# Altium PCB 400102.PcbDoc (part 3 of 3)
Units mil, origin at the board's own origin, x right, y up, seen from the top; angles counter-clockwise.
Board outline 3703.69 x 2381.89 mil, 2 copper layers (Top Layer, Bottom Layer), stack 61.8 mil thick; 220 components, 149 nets, 880 pads, 750 vias.
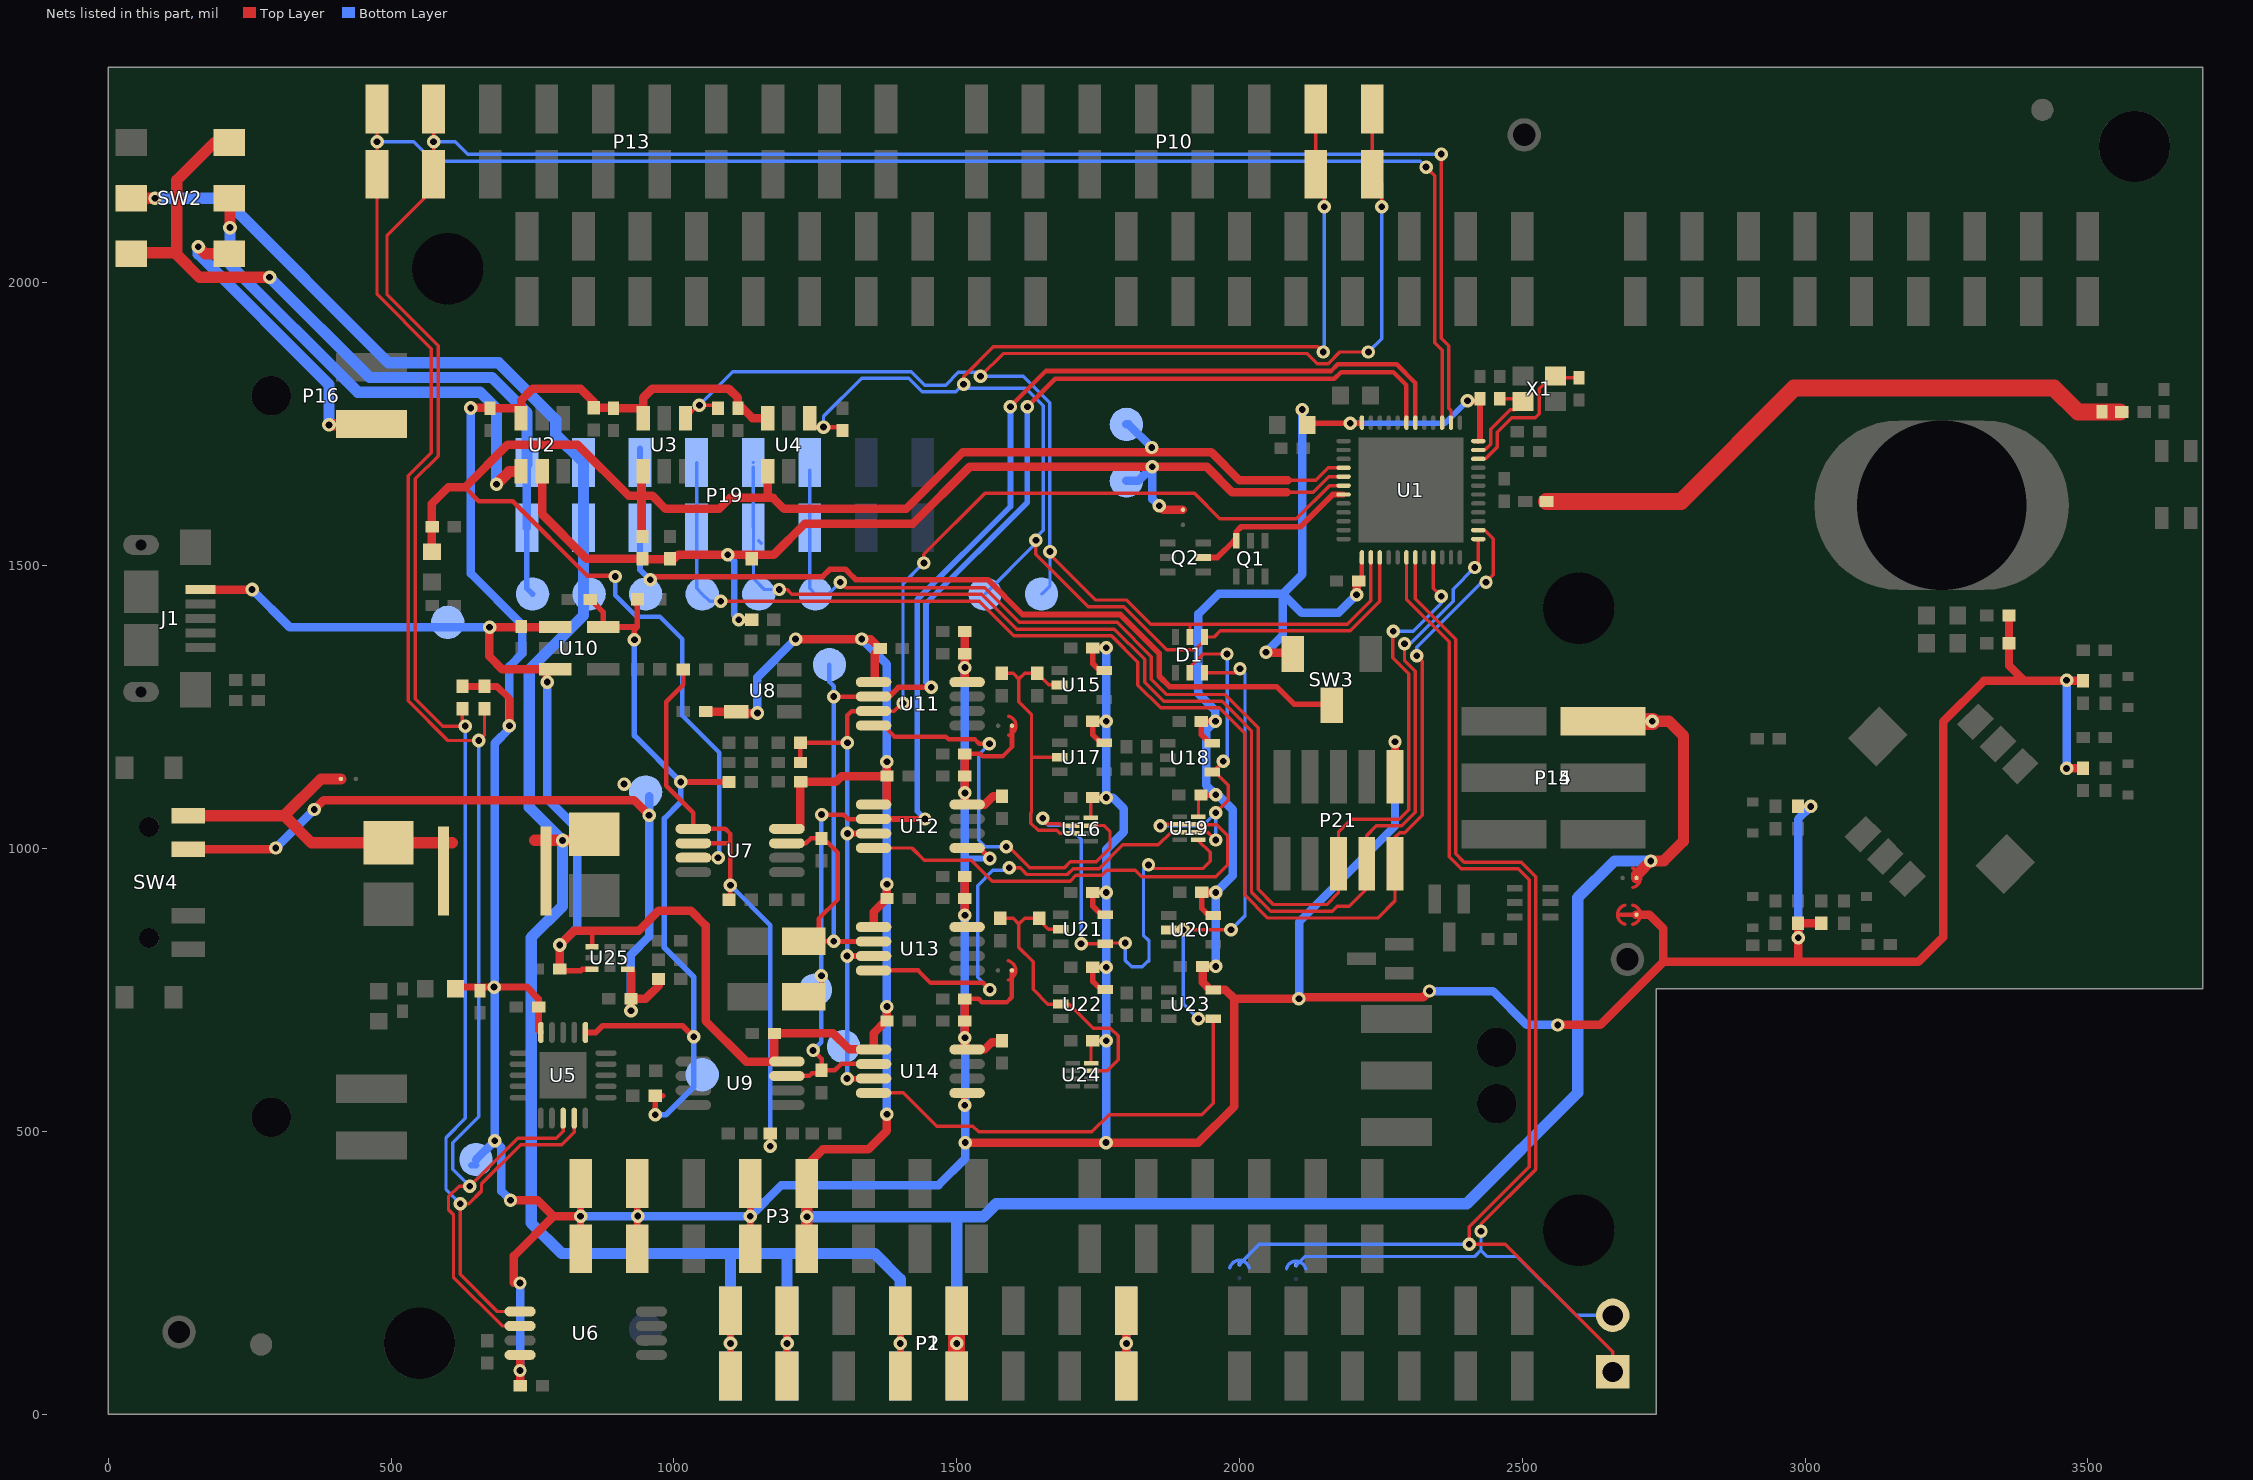
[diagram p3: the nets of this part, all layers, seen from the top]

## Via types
v1: diameter 24, hole 12, Top Layer to Bottom Layer, tented both sides, 666 vias
v2: diameter 23.62, hole 11.81, Top Layer to Bottom Layer, tented both sides, 68 vias
v3: diameter 25.98, hole 12.99, Top Layer to Bottom Layer, tented both sides, 16 vias

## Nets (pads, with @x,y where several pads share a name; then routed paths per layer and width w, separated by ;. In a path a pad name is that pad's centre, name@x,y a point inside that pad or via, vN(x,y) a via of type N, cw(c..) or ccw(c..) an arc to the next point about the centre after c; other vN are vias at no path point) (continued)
P0.05: Q1.6 Q2.2 U1.7 | length 303.6
  Top Layer w10: Q2.2@1936,1514.59 1960.59,1514.59 1989.99,1543.99 Q1.6@1994,1543.99 1994,1560 2003,1569 2108,1569 2164.98,1625.98 U1.7@2184.06,1625.98
RF: C14.2 L1.2 R7.1 | length 1114.4
  Top Layer w30: L1.2@2542.85,1613.86 2780.7,1613.86 2980.82,1813.98 3440.48,1813.98 3482.5,1771.95 R7.1@3556.93,1771.95
SCL: P13.10 R9.1 U1.39 U5.3 U6.6 | length 5047.8
  Top Layer w6: P13.10@475,2307.52 v1(475,2249.84) P13.10@475,2192.17 475,1980 571,1884 571,1700 530,1659 530,1261.16 600.16,1191 v1(655,1191) 665,1201 R9.1@665,1247.32 ; U6.6@727.86,155.8 696.2,155.8 610.09,241.91 610.09,352.91 601.28,361.72 601.28,384.28 620,403 v2(639,403) 724,488 792,488 804,500 U5.3@804,523.21 ; v1(2330,2205) 2345,2190 2345,1894.67 2358.27,1881.4 U1.39@2358.27,1752.95
  Bottom Layer w6: v1(475,2249.84) 540.16,2249.84 575,2215 2320,2215 v1(2330,2205) ; v2(639,403) 608.91,433.09 608.91,479.91 655,526 v1(655,1191)
SDA: P13.9 R8.1 U1.38 U5.4 U6.5 | length 4958.2
  Top Layer w6: P13.9@575,2307.52 v1(575,2249.84) P13.9@575,2192.17 575,2166.84 492.69,2084.53 492.69,1979.31 583,1889 583,1694 542.85,1653.85 542.85,1265.15 591.49,1216.51 v1(631,1216.51) 626,1221.51 R8.1@626,1247.32 ; U6.5@727.86,181.39 687.45,181.39 622,246.84 v2(622,372) 637.3,372 659.72,394.42 659.72,406.88 728.93,476.09 801.78,476.09 823.69,498 U5.4@823.69,523.21 ; v1(2356.91,2227.97) 2356.91,1902.19 2370.17,1888.92 2370.17,1778.41 2374.02,1774.56 U1.38@2374.02,1752.95
  Bottom Layer w6: v1(575,2249.84) 613.28,2249.84 635.16,2227.97 v1(2356.91,2227.97) ; v2(622,372) 597,397 597,489 631,523 v1(631,1216.51)
SE_OUT: C26.2 R24.2 TP12.1 U1.6 U11.3 U12.3 U13.3 U14.3 | length 2115.3
  Top Layer w6: U11.3@1352.98,1243.08 1389.08,1243.08 1403,1257 v2(1405,1257) ; v2(1442,1505) 1442,1520 1550,1628 1920.44,1628 1965.34,1583.09 2100.55,1583.09 2159.19,1641.73 U1.6@2184.06,1641.73
  Top Layer w8: C26.2@1223.69,1152.3 R24.2@1223.69,1186.89 1306.64,1186.89 v1(1306.8,1187.05) 1306.8,1235.52 1314.36,1243.08 U11.3@1352.98,1243.08
  Top Layer w10: v1(1306.23,593.12) 1352.62,593.12 U14.3@1352.98,593.48 ; v1(1306.23,810.01) U13.3@1352.98,810.01 ; v1(1306.8,1026.55) U12.3@1352.98,1026.55
  Bottom Layer w6: v2(1405,1257) 1405,1468 v2(1442,1505)
  Bottom Layer w8: v1(1306.23,593.12) v1(1306.23,810.01) 1306.8,810.58 v1(1306.8,1026.55) v1(1306.8,1187.05)
STAGE1_OUT: R39.2 R41.2 U15.2 U16.3 U17.2 | length 512.7
  Top Layer w6: R39.2@1579.77,1309.8 1600,1309.8 1610,1299.8 ; 1633.55,1161.41 U17.2@1682,1161.41 ; U15.2@1681.78,1289.41 1662.79,1289.41 R41.2@1642.41,1309.79 1620,1309.8 1610,1299.8 ; U16.3@1704.66,1026.87 1689,1026.87 1682.36,1026.87 1680.48,1028.74 1677.07,1032.15 1643.93,1032.15 1631.09,1044.99 1631.09,1062.31 1632.14,1063.35 1632.14,1237.49 1610,1259.63 1610,1299.8
STAGE2_OUT: R43.2 R45.2 U21.2 U22.2 U24.7 | length 529.3
  Top Layer w6: R43.2@1579.77,876.53 1600,876.53 1610,866.53 ; U21.2@1684.18,857.29 1662.21,857.29 1642.97,876.53 1620,876.53 1610,866.53 ; U24.7@1737.49,606.89 1765.89,606.89 1785.34,626.34 1785.34,668.66 1771.47,682.53 1741.47,682.53 1699.1,724.9 U22.2@1683.75,724.9 1661,724.9 1635,750.9 1635,800 1610,825 1610,866.53
STAGE2_OUT_INV: U16.2 U19.5 U21.4 | length 820.2
  Top Layer w6: v1@1654,1049.65 1659.59,1044.06 1682,1044.06 1685.41,1040.65 U16.2@1704.66,1040.65 ; v1(1720,831.7) U21.4@1762.92,831.7 1764.23,833 v2(1798,833) ; v2(1839,971) 1845.37,964.63 1934.82,964.63 1948,977.81 1948,993.26 1927.43,1013.83 U19.5@1927.43,1015.16
  Bottom Layer w6: v1@1654,1049.65 1663,1040.65 1696.05,1040.65 1720,1016.7 v1(1720,831.7) ; v2(1798,833) 1798,802 1809.33,790.67 1827.75,790.67 1838.08,801 1840,801 1840,837.13 1830.19,846.95 1830.19,962.19 v2(1839,971)
  other v1: 1652,1053.65
STG1_OFF_SHDN: U12.4 U19.7 | length 783.3
  Top Layer w6: U12.4@1352.98,1000.96 1420.91,1000.96 1442.86,979.01 1525.8,979.01 1562.62,942.19 1700.44,942.19 1710.82,952.57 1756.66,952.57 1765.67,961.58 1816,961.58 1827.3,950.28 1958.28,950.28 1978.72,970.72 1978.72,1023.58 1960.01,1042.28 1927.87,1042.28 U19.7@1927.43,1042.72
STG1_ON_SHDN: U11.4 U16.7 | length 731
  Top Layer w6: v1(1587.44,1003.23) 1591.79,1003.23 1629.02,966 1690.58,966 1700.96,976.38 1746.8,976.38 1770.95,1000.53 1770.95,1030.33 1760.63,1040.65 U16.7@1737.34,1040.65
  Top Layer w8: U11.4@1352.98,1217.49 1370.51,1217.49 1390,1198 1480.89,1198 1486,1192.89 1532.22,1192.89 1539.99,1185.12 v1(1557.77,1185.12)
  Bottom Layer w6: v1(1557.77,1185.12) 1538.66,1166.01 1538.66,1014.68 1550.11,1003.23 v1(1587.44,1003.23)
STG2_ON_SHDN: U13.4 U19.3 | length 819.3
  Top Layer w6: v2(1593,966) 1612.18,966 1624.09,954.09 1695.51,954.09 1705.89,964.48 1751.73,964.48 1793.63,1006.37 1856.65,1006.37 1879.21,1028.94 U19.3@1894.76,1028.94
  Top Layer w8: U13.4@1352.98,784.42 1431.65,784.42 1453.72,762.35 1547.07,762.35 v1(1558.77,750.66)
  Bottom Layer w6: v1(1558.77,750.66) 1537,772.43 1537,934.42 1564,961.42 1588.42,961.42 v2(1593,966)
SW1_ON/OFF: D1.2 P10.1 R5.2 TP3.1 U1.14 U3.4 | length 3005.8
  Top Layer w6: U3.4@1020.4,1761.22 1043.18,1784 v1(1045,1784) 1072.66,1784 R5.2@1078,1778.66 ; v1(1542,1835) 1582.28,1875.28 2119.72,1875.28 2137.72,1857.28 2156.58,1857.28 2177.3,1878 v2(2228,1878) ; v1(1665,1525) 1665,1519.38 1744.85,1439.53 1799.97,1439.53 1842.82,1396.69 1912,1396.69 ; D1.2@1912.41,1374 1912.41,1396.28 1912,1396.69 ; U1.14@2232.28,1514.76 2232.28,1438.12 2190.85,1396.69 1912,1396.69 ; P10.1@2235,2307.52 P10.1@2235,2192.17 2251.41,2175.75 v1(2251.41,2135)
  Bottom Layer w6: v1(1045,1784) 1104.19,1843.19 1419.97,1843.19 1443.67,1819.49 1480.49,1819.49 1502.91,1841.91 1536.52,1841.91 v1@1543.43,1835 ; v1(1542,1835) v1@1543.43,1835 ; TP3.1@1650,1450 1665,1465 v1(1665,1525) 1664.57,1525.43 1664.57,1788.09 1617.65,1835 v1@1543.43,1835 ; v2(2228,1878) 2251.41,1901.41 v1(2251.41,2135)
SW1_ON/OFF_AUTO: D1.5 U18.4 U19.2 U19.6 | length 628
  Top Layer w6: v1(1860,1040) 1862.72,1042.72 U19.2@1894.76,1042.72 ; D1.5@1912.41,1311.01 1912.41,1320.41 1936,1344 v2(1978,1344) ; U19.6@1927.43,1028.94 1944.06,1028.94 v2(1958,1015) ; v2(1958,1063) 1980,1085 1980,1112 1957.03,1134.97 U18.4@1952.15,1134.97 v1(1971.34,1154.16)
  Bottom Layer w6: v1(1860,1040) 1935,1040 v2(1958,1063) v2(1958,1015) ; v1(1971.34,1154.16) 1978.29,1161.11 1978.29,1343.71 v2(1978,1344)
SW2_ON/OFF: D1.1 P10.2 R6.1 TP4.1 U1.15 U4.4 | length 2837.3
  Top Layer w6: v1(1512.09,1821) 1512.09,1834.65 1564.62,1887.19 2138.81,1887.19 v2(2148,1878) ; v1(1640,1545) 1640,1520.44 1732.81,1427.62 1795.04,1427.62 1871.35,1351.31 1922,1351.31 1938,1367.31 D1.1@1938,1374 1955,1374 1965.78,1384.78 2195.78,1384.78 2248.03,1437.03 U1.15@2248.03,1514.76 ; P10.2@2135,2307.52 P10.2@2135,2192.17 2150,2177.16 v1(2150,2135)
  Top Layer w8: U4.4@1240.4,1761.22 1243,1758.62 1243,1747.86 1245.6,1745.26 v1(1264.42,1745.26) 1292.03,1745.26 R6.1@1298,1739.29
  Bottom Layer w6: v1(1264.42,1745.26) 1264.42,1764 1331.7,1831.28 1415.04,1831.28 1438.74,1807.58 1498.67,1807.58 v1(1512.09,1821) ; v1@1517.99,1814.09 1621.72,1814.09 1652.66,1783.15 1652.66,1562.5 1640,1549.84 v1(1640,1545) 1640,1540 TP4.1@1550,1450 ; v2(2148,1878) 2150,1880 v1(2150,2135)
SW2_ON/OFF_AUTO: D1.6 U14.4 U20.2 U23.4 | length 1645.4
  Top Layer w6: U14.4@1352.98,567.89 1405.68,567.89 1464.66,508.91 1528.6,508.91 1538.6,498.91 1738.91,498.91 1769.41,529.41 1932.92,529.41 1953.36,549.85 U23.4@1953.36,698.95 v1(1927.43,698.95) ; U20.2@1874.62,856.27 v1(1900.57,856.27) v1(1985,856.27) ; D1.6@1938,1311.01 1994.01,1311.01 v2(2001,1318)
  Bottom Layer w6: v1(1900.57,856.27) 1900.57,725.81 v1(1927.43,698.95) ; v1(1985,856.27) 2009.74,881.02 2009.74,1309.26 v2(2001,1318)
SWDCLK: P19.5 P21.4 TP7.1 U1.25 | length 2486.7
  Top Layer w6: v2(1186,1458) 1200,1458 1208.5,1449.5 1544.34,1449.5 1605.93,1387.91 1778.59,1387.91 1832.19,1334.31 1832.19,1294.03 1865.7,1260.51 1969.32,1260.51 1997.42,1232.42 2021.19,1208.65 2021.19,923.1 2055.24,889.05 2164,889.05 2172.95,898 2194,898 2225,929 P21.4@2225,973.23 2225,1023 2242.09,1040.09 2287.31,1040.09 2311,1063.78 2311,1313.87 2291.72,1333.15 v2(2291.72,1362) ; v2(2416,1497) 2422.24,1503.24 U1.25@2422.24,1547.24
  Bottom Layer w6: P19.5@1140,1673.98 P19.5@1140,1567.32 1140.75,1566.57 1140.75,1477.25 1160,1458 v2(1186,1458) ; P19.5@1150,1543.98 P19.5@1154.1,1539.88 ; v2(2291.72,1362) 2302.3,1362 2377.72,1437.42 2377.72,1458.72 v2(2416,1497)
SWDIO: P19.4 P21.2 TP6.1 U1.26 | length 2665.7
  Top Layer w6: v2(1083,1437) 1540,1437 1601,1376 1773.66,1376 1820.28,1329.38 1820.28,1289.1 1860.77,1248.61 1964.39,1248.61 2009.28,1203.72 2009.28,918.17 2050.36,877.09 2244.56,877.09 2275,907.53 P21.2@2275,973.23 2275,1020 2283.19,1028.19 2292.24,1028.19 2322.91,1058.85 2322.91,1331.53 v1(2313.43,1341) ; U1.26@2422.24,1562.99 2433.65,1562.99 2449,1547.64 2449,1484 v2(2436,1471)
  Bottom Layer w6: P19.4@1040,1682.68 P19.4@1040,1567.32 1040,1460 TP6.1@1050,1450 1063,1437 v2(1083,1437) ; v1(2313.43,1341) 2313.43,1356.3 2428.13,1471 v2(2436,1471)
SWO: P19.6 P21.6 TP8.1 U1.21 | length 2360.1
  Top Layer w6: v2(1294,1471) 1303.6,1461.4 1549.27,1461.4 1610.86,1399.81 1783.52,1399.81 1844.09,1339.24 1844.09,1298.96 1870.64,1272.42 1974.26,1272.42 2033.09,1213.58 2033.09,928.03 2060.17,900.96 2153.96,900.96 2175,922 P21.6@2175,973.23 2175,1029 2198,1052 2282.38,1052 2299.09,1068.72 2299.09,1308.94 2271,1337.03 2271,1383 v2(2272,1384) ; U1.21@2342.52,1514.76 2342.52,1460.48 v2(2357,1446)
  Bottom Layer w6: P19.6@1240,1668.98 P19.6@1240,1567.32 1240,1460 TP8.1@1250,1450 1273,1450 v2(1294,1471) ; v2(2272,1384) 2307.46,1384 2357,1433.54 v2(2357,1446)
SYNC1: P7.1 SB3.1 U1.18 | length 2196.2
  Top Layer w6: U1.18@2295.28,1514.76 2295.28,1440.72 2370.72,1365.28 2370.72,985.45 2392.07,964.09 2493.07,964.09 2512.09,945.07 2512.09,437.39 2406,331.3 v2(2406,300) 2470,300 2660,110 P7.1@2660,74.68
  Bottom Layer w6: SB3.1@2000,265 2035,300 v2(2406,300)
SYNC2: P7.2 SB4.1 U1.19 | length 2031.1
  Top Layer w6: U1.19@2311.02,1514.76 2311.02,1441.81 2382.62,1370.21 2382.62,990.38 2397,976 2498,976 2524,950 2524,432.46 2427,335.46 v2(2427,323)
  Bottom Layer w6: SB4.1@2100,263.36 2115.17,278.54 2415.54,278.54 2427,290 ; v2(2427,323) 2427,290 ; P7.2@2660,174.68 2595.32,174.68 2491.46,278.54 2438.46,278.54 2427,290
V5V: C23.2 C24.2 C28.2 C30.2 C32.1 C36.1 C41.1 C45.1 C59.1 J1.1 P1.5 P2.5 P3.5 P14.2 P15.2 SB8.1 TP16.1 U7.8 U8.5 U9.8 U10.1 U10.3 U11.1 U12.1 U13.1 U14.1 U25.1 U25.3 | length 7396.5
  Top Layer w8: U25.1@855.13,826.2 855.13,854.87
  Top Layer w10: C59.1@798.13,786.83 801.35,783.61 834.9,783.61 838.12,786.83 U25.3@855.13,786.83
  Top Layer w15: J1.1@163,1458 v1(254,1458) ; v1(776,1294.26) 775,1295.26 775,1316.96 696.2,1316.96 673.59,1339.57 673.59,1390.94 v1(674,1391.35) 787.39,1391.35 788.99,1392.94 U10.1@790.17,1391.77 ; C59.1@798.13,786.83 v1(798.13,829.43) 823.71,855 937.89,855 972.89,890 1030.09,890 1055.92,864.17 1055.92,695.13 1127.79,623.25 U9.8@1199.55,623.25 ; C24.2@1055.92,1240 C24.2@1057.92,1242.01 ; C24.2@1055.92,1242 C24.2@1057.92,1242.01 ; U8.5@1109.76,1241.6 1109.35,1242.01 C24.2@1057.92,1242.01 ; U8.5@1123.25,1242.85 1123.25,1239.6 v1(1147.56,1239.6) ; U9.8@1177.69,627.98 C30.2@1177.69,673.2 1281.8,673.2 1310.34,644.66 U14.1@1352.98,644.66 1352.98,673.2 C45.1@1374.63,694.85 ; U7.8@1199.68,1034.89 1223.58,1034.89 C23.2@1223.58,1117.75 ; v1(1215.18,1370.41) v2(1332,1370.41) 1347.65,1370.41 C32.1@1364.6,1353.46 1355,1343.86 U11.1@1355,1296.29 ; C23.2@1223.93,1118.1 1286.49,1118.1 1296.31,1127.93 C36.1@1376.6,1127.93 ; P3.5@1235,407.52 1235,440 1263,468 1343.59,468 1376.6,501 v1(1376.6,530) ; U13.1@1352.98,861.19 1352.98,887.77 C41.1@1376.6,911.39 v1(1376.6,936.98) ; U12.1@1352.98,1077.73 1374.33,1077.73 1376.6,1080 C36.1@1376.6,1127.93 ; C45.1@1376.6,694.85 v1(1376.6,720.45) ; v1(1376.6,1153.52) C36.1@1376.6,1127.93
  Top Layer w20: v1@1235,348.92 P3.5@1235,407.52 ; P3.5@1235.08,292.25 v1(1235.08,349) ; SB8.1@2702.58,948 2702.58,953.58 2706.24,957.24 v2(2727,978) 2750,978 2785,1013 2785,1199.35 2759.35,1225 v1(2730,1225)
  Top Layer w30: P2.5@1500,67.32 v1(1500,125) P2.5@1500,182.68 ; P15.2@2642.5,1225 v1(2730,1225)
  Bottom Layer w15: v1(254,1458) 320.65,1391.35 v1(674,1391.35) ; v1(776,1294.26) 776,1088 829,1035 829,860.29 v1(798.13,829.43) ; v1(1147.56,1239.6) 1147.31,1239.85 1147.31,1302.54 v1(1215.18,1370.41) ; v2(1332,1370.41) 1376.6,1325.81 v1(1376.6,1153.52) v1(1376.6,936.98) v1(1376.6,720.45) v1(1376.6,530)
  Bottom Layer w20: v1(1235.08,349) 1547.08,349 1569.91,371.83 2401.83,371.83 2598,568 2598,913 2663,978 v2(2727,978) ; P1.5@1500,67.32 v1(1500,125) P1.5@1500,182.68 1500,342 ; P14.2@2666.22,1225 v1(2730,1225)
VDD: C5.1 C8.1 C9.1 C11.1 C12.1 C13.1 C16.2 C17.1 C31.2 C33.2 C35.2 C37.2 C40.2 C42.2 C44.2 C46.2 C47.2 C48.2 C49.2 C50.2 C51.2 C52.2 C53.2 C54.2 C55.2 C56.2 C67.2 FB2.2 P3.1 P3.2 P3.4 P21.1 R1.2 R8.2 R9.2 R10.2 R12.2 R13.2 R14.2 R15.2 R16.2 R17.2 R42.2 R46.2 SB5.1 SB6.1 SB7.1 SW3.1 TP18.1 U1.13 U1.36 U1.48 U2.6 U3.6 U4.6 U5.15 U6.8 U11.8 U12.5 U12.8 U13.8 U14.5 U14.8 U15.5 U16.8 U17.5 U18.5 U19.8 U20.5 U21.5 U22.5 U23.5 U24.8 | length 13533
  Top Layer w6: U16.8@1737.34,1054.43 1737.34,1086.5 C47.2@1740.83,1090 ; U24.8@1737.49,620.67 C51.2@1737.49,656.66 ; U19.8@1927.43,1056.5 1927.43,1089.77 C50.2@1932.05,1094.38
  Top Layer w8: C44.2@1514.39,734.23 1538.66,734.23 1544.32,728.57 1588.87,728.57 1597.46,737.16 SB6.1@1597.46,784.42 ; C35.2@1514.39,1167.3 1541.72,1167.3 1546.17,1162.84 1580.98,1162.84 1597.77,1179.63 SB5.1@1597.77,1217.12 ; C5.1@2210.83,1472.86 2216.54,1478.56 U1.13@2216.54,1514.76
  Top Layer w9: C9.1@2123.23,1751.97 v1(2195.76,1751.97) U1.48@2216.15,1751.97
  Top Layer w10: v1(1514.39,546.23) 1514.39,563.94 U14.5@1518.33,567.89 ; U12.5@1518.33,1000.96 1540.14,1000.96 v1(1558.77,982.33) ; C47.2@1740.83,1090 v1(1764.44,1090) ; C53.2@1740.83,1354.37 1740.83,1326.63 1752.47,1315 U15.5@1760.52,1315 ; U17.5@1760.74,1187 1754.82,1187 1740.84,1200.99 C48.2@1740.84,1225 v1(1764.44,1225) ; U22.5@1762.49,750.49 1755.3,750.49 1740.84,764.95 C52.2@1740.84,790 v1(1764.44,790) ; U21.5@1762.92,882.88 1755.91,882.88 1740.83,897.95 C56.2@1740.83,922.5 1764.15,922.5 v1(1764.44,922.21) ; C50.2@1932.05,1094.38 1957.38,1094.38 v1(1958,1095) ; C54.2@1933.43,922.62 1933.43,894.2 1945.77,881.86 U20.5@1953.36,881.86 ; U18.5@1952.15,1186.16 1947.71,1186.16 1932.59,1201.27 C49.2@1932.59,1224.74 v1@1957.12,1224.74 ; v1(2403.12,1791.86) 2398.52,1791.86 2397.83,1791.17 2425.15,1791.17 2425.15,1723.38 U1.36@2422.24,1720.47
  Top Layer w12: FB2.2@618.49,755 v1(682,755) 740,755 760.69,734.31 C16.2@760.69,720 760.69,678.73 U5.15@764.63,674.79 ; R8.2@626,1286.69 R9.2@665,1286.69 687.31,1286.69 709,1265 v1(709,1217) v1@709.49,1216.51 ; P3.1@835,292.17 v1(835,349.85) P3.1@835,407.52 ; P3.2@935,292.17 P3.2@935,407.52 ; P3.4@1135,292.17 v1(1135,349.85) P3.4@1135,407.52 ; C53.2@1740.83,1354.37 1741.47,1355 v1(1764.44,1355) ; U23.5@1948.23,750.13 U23.5@1953.36,750.13
  Top Layer w15: v1(640.84,1778.98) C11.1@674.68,1778.98 ; C11.1@675,1778.66 725.57,1778.66 729.6,1774.63 U2.6@729.6,1761.22 729.6,1792.42 750.18,1813 834.88,1813 858,1789.88 R1.2@858,1779.45 892.21,1779.45 C12.1@893,1778.66 938.49,1778.66 U3.6@945.6,1771.55 ; v2(711,378) 759,378 787.15,349.85 ; v2@716.86,231.86 716.86,279.55 787.15,349.85 ; C17.1@727.86,50.46 v2(727.86,77) U6.8@727.86,104.61 ; v1(835,349.85) 787.15,349.85 ; U3.6@945.6,1761.22 U3.6@945.6,1771.55 ; C13.1@1113,1778.66 1113,1797 1097,1813 961.56,1813 945.6,1797.04 U3.6@945.6,1771.55 ; C13.1@1121,1778.98 1138.76,1761.22 U4.6@1165.6,1761.22 ; C44.2@1514.39,734.23 C46.2@1514.39,694.85 v1(1514.39,665.33) 1514.39,645.64 1515.38,644.66 U14.8@1518.33,644.66 1549.33,644.66 1561.71,657.04 1579.96,657.04 1580.07,657.15 R46.2@1580.07,660.24 ; v1(1514.39,881.86) C42.2@1514.39,911.39 C40.2@1514.39,950.76 ; U12.8@1514.39,1081.67 v1(1514.39,1098.4) C37.2@1514.39,1127.93 C35.2@1514.39,1167.3 ; U11.8@1514.39,1298.2 v1(1514.39,1320) C33.2@1514.39,1344.46 C31.2@1514.39,1383.83 ; v1(1515,480) v1(1764,480) 1927.16,480 1991,543.84 1991,734.26 ; U12.8@1518.33,1077.73 1549.5,1077.73 1564.26,1092.49 R42.2@1580.07,1092.49 ; C54.2@1933.43,922.62 1933.84,922.21 v1(1958,922.21) ; U23.5@1948.23,750.13 1934.68,763.67 C55.2@1934.68,791.49 v1(1958,791.49) ; U23.5@1953.36,750.13 1975.13,750.13 1991,734.26 ; v2(2047,1347) 2048.05,1345.95 SW3.1@2094.1,1345.95 ; v1(2207.15,1448.86) 2207.15,1469.17 C5.1@2210.83,1472.86 ; P21.1@2275,1126.77 v2(2275,1189) ; v2(2336,748) 2325.06,737.06 2107.8,737.06 v1(2105,734.26) 1991,734.26 ; v2(2563,688) 2638,688 2749.41,799.41 ; SB7.1@2701,883 2725,883 2749.41,858.59 2749.41,799.41 ; R14.2@3028.82,867.83 R17.2@2987.64,867.83 2988,867.47 v2(2988,841.97) 2988,799.41 ; R10.2@3360.69,1412.13 R12.2@3360.69,1362.95 3360.69,1323.46 3387.73,1296.43 ; v1(3462.6,1141.73) 3462.93,1142.06 R16.2@3491.42,1142.06 ; R13.2@3491.42,1296.43 3387.73,1296.43 ; 2749.41,799.41 2988,799.41 ; 2988,799.41 3200.2,799.41 3244,843.2 3244,1224.15 3316.27,1296.43 3387.73,1296.43
  Top Layer w20: C11.1@674.68,1778.98 C11.1@675,1778.66
  Bottom Layer w10: 1514.39,981.12 1515.6,982.33 v1(1558.77,982.33) ; v1(2195.76,1751.97) 2363.23,1751.97 v1(2403.12,1791.86)
  Bottom Layer w12: TP18.1@641.66,440 TP18.1@650,440
  Bottom Layer w15: v1(640.84,1778.98) 640.84,1486.16 731.67,1395.33 731.67,1344.76 709,1322.09 v1(709,1217) 709,1212 683.08,1186.08 v2(683.08,483.08) ; TP18.1@650,450 v2(683.08,483.08) ; v2(711,378) 694.78,394.22 694.78,471.37 v2(683.08,483.08) ; v2(727.86,77) v2(727.86,231.86) ; v1(835,349.85) 935.85,349.85 v1(936,350) 1134.84,350 v1(1135,349.85) 1190.15,405 1467.99,405 1515,452.01 v1(1515,480) v1@1515,664.72 ; v1(1514.39,665.33) v1(1514.39,881.86) 1514.39,981.12 v1(1514.39,1098.4) v1(1514.39,1320) ; v1@1764.44,480.44 v1(1764.44,660) v1(1764.44,790) v1(1764.44,922.21) 1764.44,998.44 1795.41,1029.41 1795.41,1070.52 1775.93,1090 v1(1764.44,1090) v1(1764.44,1225) v1(1764.44,1355) ; v1(1958,791.49) v1(1958,922.21) 1988,952.21 1988,1068.66 1961.66,1095 v1(1958,1095) 1941.04,1111.96 1941.04,1208.65 v1(1957.38,1225) 1957.38,1243.72 1927.43,1273.67 1927.43,1414.72 1963.07,1450.36 2076.44,1450.36 ; v2(2047,1347) 2076.44,1376.44 2076.44,1450.36 ; v1(2105,734.26) 2106.1,735.36 2106.1,870.72 2275,1039.61 v2(2275,1189) ; v1(2110.87,1776.11) 2110.87,1484.79 2076.44,1450.36 ; v1(2207.15,1448.86) 2175.29,1417 2109.79,1417 2076.44,1450.36 ; v2(2336,748) 2448,748 2508,688 v2(2563,688) ; v2(2988,841.97) 2987.64,842.33 2987.64,1051.96 v1(3010.17,1074.49) ; v1(3462.6,1141.73) v1(3462.6,1297.65)
  Bottom Layer w20: v1(1514.39,665.33) v1@1515,664.72
VDD_DUT: SW2.5 U2.1 | length 883
  Top Layer w20: v1@213.61,2099.39 v1(215,2098) 215,2148.61 SW2.5@213.61,2150 ; v2(686.16,1644) 708.9,1666.73 U2.1@729.6,1666.73
  Bottom Layer w20: v1(215,2098) 215,2033 441,1807 656.95,1807 686.16,1777.79 v2(686.16,1644)
VDD_DUT': R2.2 R3.2 R4.2 R25.1 SB2.1 TP2.1 U1.5 U2.2 | length 1931
  Top Layer w6: 2084,1630 2130.62,1630 2158.1,1657.48 U1.5@2184.06,1657.48
  Top Layer w12: R2.2@943,1516.42 R2.2@944.67,1514.74
  Top Layer w15: U2.2@767,1666.73 767,1591 845.81,1512.19 R2.2@944.31,1512.19 ; R2.2@944.67,1514.74 947.63,1511.79 999.56,1511.79 1007.18,1519.42 v1(1095,1519.42) 1176.41,1519.42 1231.52,1574.54 1422.54,1574.54 1523,1675 v2(1846,1675) 1942,1675 1987,1630 2084,1630 ; R4.2@1133.08,1511.79 R4.2@1137.75,1516.46 ; v2(1858,1606) 1865,1599 SB2.1@1900,1599
  Bottom Layer w12: v1(1095,1519.42) 1106.72,1507.7 1106.72,1412.5 v1(1114.58,1404.64)
  Bottom Layer w15: TP2.1@1800,1650 1821,1650 v2(1846,1675) 1846,1618 v2(1858,1606)
VDD_DUT_DK: P19.1 SW2.1 SW2.6 TP21.1 | length 1394.7
  Top Layer w20: SW2.1@40.39,2051.57 42.31,2053.5 117.5,2053.5 121,2050 ; SW2.6@213.61,2248.43 187.43,2248.43 121,2182 121,2050 ; v1(285,2010) 161,2010 121,2050
  Bottom Layer w10: P19.1@740,1567.32 740,1460 TP21.1@750,1450
  Bottom Layer w15: P19.1@740,1567.32 P19.1@740,1678.98
  Bottom Layer w20: v1(285,2010) 462.09,1832.91 678.09,1832.91 740,1771 P19.1@740,1682.68 P19.1@740,1678.98
VDD_DUT_EXT: P16.2 SW2.4 | length 546
  Top Layer w15: P16.2@463.28,1749.14 P16.2@465,1750.86
  Top Layer w20: v2(159,2064) 171.43,2051.57 SW2.4@213.61,2051.57 ; v1(390,1749.14) P16.2@463.28,1749.14
  Bottom Layer w20: v2(159,2064) 159,2051 390,1820 v1(390,1749.14)
VDD_DUT_PRE: C65.2 FB1.2 R2.1 TP1.1 U1.4 U3.1 U4.1 U7.3 | length 3087
  Top Layer w6: U3.1@944.6,1658.98 945.13,1658.45 U3.1@945.6,1658.92 ; 2085,1651 2134.78,1651 2157.01,1673.23 U1.4@2184.06,1673.23
  Top Layer w8: 630.54,1638.54 655.08,1614 715,1614 847,1482 895,1482 v2(896,1481) ; U7.3@1034.32,983.71 v1(1078,983.71)
  Top Layer w15: FB1.2@572,1524.57 572,1610 600.54,1638.54 630.54,1638.54 705.98,1713.98 829.75,1713.98 919.75,1623.98 943,1623.98 ; U3.1@943,1664.13 943,1623.98 ; R2.1@944.31,1551.56 943,1552.86 943,1623.98 ; U3.1@945.6,1658.92 U3.1@945.6,1666.73 ; U4.1@1165.6,1666.73 1165.6,1619.88 ; v2(1845,1709) v2@1845,1701 ; 2085,1651 1999.96,1651 1949.96,1701 v2@1845,1701 ; 943,1623.98 961.65,1623.98 985.13,1600.5 1079.8,1600.5 1099.18,1619.88 1165.6,1619.88 ; 1165.6,1619.88 1175.26,1619.88 1194.65,1600.5 1410.5,1600.5 1511,1701 v2@1845,1701
  Bottom Layer w8: v2(896,1481) 896,1448 934,1410 975.21,1410 1015,1370.21 1015,1234.6 1079.83,1169.77 1079.83,985.54 v1(1078,983.71)
  Bottom Layer w15: TP1.1@1800,1750 1804,1750 v2(1845,1709)
VDK: C61.1 L2.1 P1.1 P1.2 P1.4 P2.1 P2.2 P2.4 P19.2 SW2.2 TP20.1 | length 4193.7
  Top Layer w12: P2.1@1100,67.32 v1(1100,125) P2.1@1100,182.68 ; P2.2@1200,67.32 v1(1200,125) P2.2@1200,182.68 ; P2.4@1400,67.32 v1(1400,125) P2.4@1400,182.68
  Top Layer w20: SW2.2@40.39,2150 v2(82.47,2150) ; 753.76,1014.68 802.45,1014.68 v1(803,1014.13) C61.1@862,1014.13
  Bottom Layer w12: P1.1@1100,67.32 v1(1100,125) P1.1@1100,182.68 ; P1.2@1200,67.32 v1(1200,125) P1.2@1200,182.68 ; P1.4@1400,67.32 v1(1400,125) P1.4@1400,182.68
  Bottom Layer w20: v2(82.47,2150) 204,2150 495.19,1858.81 690.19,1858.81 791,1758 791,1731.68 P19.2@840,1682.68 P19.2@840,1567.32 840,1411.95 744,1315.95 744,1073.13 v1(803,1014.13) 803,898 747.46,842.46 747.46,447.74 747.72,447.48 747.72,424.52 747.46,424.26 747.46,338.12 801.6,283.98 1100,283.98 ; P1.1@1100,182.68 1100,283.98 ; P1.2@1200,182.68 1200,283.98 ; P1.4@1400,182.68 1400,238.98 1355,283.98 1100,283.98
VDK': C62.1 L2.2 SB1.1 SW4.1 | length 609.2
  Top Layer w20: SW4.1@145.9,1058.11 310.89,1058.11 ; SB1.1@411,1123 375.78,1123 310.89,1058.11 ; 608.19,1009.95 C62.1@495,1009.95 359.05,1009.95 310.89,1058.11
VIN: P1.8 P2.8 | length 230.7
  Top Layer w15: P2.8@1800,67.32 v1(1800,125) P2.8@1800,182.68
  Bottom Layer w15: P1.8@1800,67.32 v1(1800,125) P1.8@1800,182.68
VREF_OFF: C39.1 R38.2 TP15.1 U1.42 U9.7 U12.2 U14.2 | length 2519.2
  Top Layer w8: U9.7@1199.68,597.8 1239.35,597.8 1243.88,602.32 1255.64,602.32 R38.2@1261,607.69 ; C39.1@1229.23,738 1229.23,736.6 1260.83,736.6 v1(1260.83,775) ; v2(1246,643) 1261,628 R38.2@1261,607.69 ; v1(1261,1060) 1300.51,1060 1308.37,1052.14 U12.2@1352.98,1052.14 ; U14.2@1352.98,619.07 1295.93,619.07 1284.55,607.69 R38.2@1261,607.69 ; v1(1595,1781) 1595,1781.98 1657.4,1844.38 2161.93,1844.38 2173.83,1856.28 2278.04,1856.28 2311.02,1823.3 U1.42@2311.02,1752.95
  Top Layer w10: U12.2@1352.98,1052.14 v2(1443.86,1052.14)
  Bottom Layer w8: v2(1246,643) 1260.57,657.57 1260.57,703.74 1260.83,704 v1(1260.83,775) 1260.83,1059.83 v1(1261,1060)
  Bottom Layer w10: v2(1443.86,1052.14) 1429.91,1066.09 1429.91,1439.79 1595,1604.89 v1(1595,1781)
VREF_ON: C38.1 R31.2 TP14.1 U1.43 U7.7 U11.2 U13.2 | length 2416.2
  Top Layer w8: U7.7@1199.68,1009.3 1233.35,1009.3 1241.81,1017.76 1265.01,1017.76 1290,992.77 1290,910 1255.63,875.63 C38.1@1255.63,836 ; C38.1@1229.23,836 C38.1@1255.63,836 ; v1(1282.73,1268.73) 1282.79,1268.67 U11.2@1352.98,1268.67 ; U13.2@1352.98,835.6 1283.13,835.6 v1(1282.73,836) C38.1@1255.63,836 ; v1(1625,1781) 1674.47,1830.47 2167.69,1830.47 2179.59,1842.38 2272.28,1842.38 2295.28,1819.38 U1.43@2295.28,1752.95
  Top Layer w10: U11.2@1352.98,1268.67 1380.67,1268.67 1397,1285 v2(1455,1285)
  Bottom Layer w8: TP14.1@1275,1325 1275,1295 1282.91,1287.09 1282.91,836.17 v1(1282.73,836)
  Bottom Layer w10: v2(1455,1285) 1445.81,1294.19 1445.81,1433.2 1625,1612.39 v1(1625,1781)
VREF_PRE: R23.1 R28.2 R35.2 U7.1 U7.2 | length 1083
  Top Layer w8: R23.1@1016.55,1316.4 1016.55,1289.79 986.45,1259.69 986.45,1111.24 1034.32,1063.37 U7.1@1034.32,1034.89 1090.75,1034.89 1099.91,1025.74 v1(1099.91,935) 1099.91,911.76 R28.2@1097.4,909.25 R28.2@1099.91,906.74 ; U7.2@1034.32,1009.3 1099.66,1009.3 ; v1(1170.32,473.37) R35.2@1170.32,496
  Bottom Layer w8: v1(1099.91,935) 1170.32,864.59 v1(1170.32,473.37)
VREG: C58.1 R47.2 SW4.2 TP17.1 U25.4 | length 1396.6
  Top Layer w8: U25.4@918.12,786.83 U25.4@920.98,783.97
  Top Layer w15: SW4.2@145.9,999.06 294.06,999.06 v2(296,1001) ; v2(364,1069) 380.68,1085.68 929.32,1085.68 v1(956,1059) v1@955.11,1058.11 ; v1(924,713) C58.1@924,734.2 ; U25.4@924.13,783.97 C58.1@924.13,734.33 950,734.33 972.76,757.1 R47.2@972.76,769.33
  Bottom Layer w15: v2(296,1001) v2(364,1069) ; v1(924,713) 923.59,713.41 923.59,811.95 956,844.36 TP17.1@956,1092.49
  other v1: 911.78,1114
VREG_REF: C29.2 R27.1 R30.2 R33.2 TP13.1 U5.11 U10.5 | length 1476.7
  Top Layer w10: U5.11@843.37,674.79 861.66,674.79 873.59,686.72 1015.32,686.72 v2(1035.04,667) ; C29.2@852.17,1440.66 874.81,1418.02 U10.5@874.81,1391.77 935.4,1391.77 ; v1(930,1369.2) 930,1386.36 935.4,1391.77 ; R30.2@935.45,1440.66 935.4,1391.77 ; v2(966.69,529.31) R33.2@966.69,563 980,563 ; v1(1012.13,1117.75) R27.1@1097.4,1117.75
  Bottom Layer w10: v1(930,1369.2) 930,1199.88 v1(1012.13,1117.75) 1012.13,1082.13 983,1053 983,824.63 1035.04,772.59 v2(1035.04,667) 1035.04,578.38 985.98,529.31 v2(966.69,529.31)
VTG: P19.3 SW3.2 TP19.1 | length 1574.9
  Top Layer w10: v2(958,1475) 963.72,1480.72 1262.72,1480.72 1275.72,1493.72 1303.41,1493.72 1316.72,1480.41 1316.72,1480.28 1321.69,1475.31 1555.03,1475.31 1616.62,1413.72 1789.28,1413.72 1858,1345 1858,1304.72 1876.4,1286.32 2065.68,1286.32 2096.6,1255.4 SW3.2@2163,1255.4
  Bottom Layer w10: P19.3@940,1707.28 P19.3@940,1682.68 P19.3@940,1567.32 940,1493 v2(958,1475)
XC1: C1.1 U1.34 X1.1 | length 268.7
  Top Layer w6: U1.34@2422.24,1688.98 2435,1688.98 2456.04,1710.02 2456.04,1736.33 2481.57,1761.86 2523.15,1761.86 2530.15,1768.86 2530.15,1812.86 X1.1@2552.79,1835.5 ; X1.1@2563.84,1832.38 C1.1@2600.15,1832.38
XC2: C2.1 U1.35 X1.3 | length 166.9
  Top Layer w6: U1.35@2422.24,1704.72 2433.65,1704.72 2444.04,1715.11 2444.04,1741.3 2478.85,1776.11 X1.3@2486.9,1776.11 ; C2.1@2458.15,1795.17 2495.81,1795.17 X1.3@2503.68,1787.3 ; X1.3@2492.6,1789.86 X1.3@2501.13,1789.86
pads on no net: D1.3 D1.4 Fid1.0 Fid2.0 J1.2 J1.3 J1.4 J1.6@57.69,1277.05 J1.6@57.69,1536.89 P3.8 P6.1 P6.2 P6.3 P6.4 P6.5 P6.6 P10.6 P10.7 P10.8 P13.1 P13.8 P16.0 P19.7 P19.8 P20.0 P21.7 P21.8 P21.10 P22.0 Q2.1 Q2.5 Q2.6 SW1.0 SW2.3 SW4.0 U1.44 U1.47 U2.5 U3.5 U4.5 U5.1 U5.8 U5.9 U5.12 U5.13 U5.19 U5.20 U15.1 U17.1 U18.1 U20.1 U21.1 U22.1 U23.1 U24.3 U24.5 U24.6
copper on no net:
  other v1: 2644,2102

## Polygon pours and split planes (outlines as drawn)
GND on Bottom Layer "Bottom_Layer-GND" (solid, remove dead copper, pour order 6): -410.29,-164.16 -410.29,2626.47 -400.99,2642.7 3905,2642.7 3905,-164.16
GND on Top Layer "Top_Layer-GND" (solid, remove dead copper, pour order 8): -140.68,-154.32 -140.68,2566.39 -132.15,2582.2 3900,2582.2 3900,-154.32

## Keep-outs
Keep-Out Layer:
  circle w6: c2600,325 r94.49
  circle w6: c600,2025 r94.49
  circle w6: c2600,1425 r94.49
  circle w6: c550,125 r94.49
  circle w6: c3582.68,2241.54 r94.49
  lines w6: 0,0 0,2381.89 3703.69,2381.89 3703.69,752.03 2736.92,752.03 2736.92,0 2600,0 0,0

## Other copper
Top Layer:
  rectangle net GND: 3609.02,1534.23 3690.43,1564.96
  rectangle net GND: 3655.87,1722.44 3690.43,1751.77
  pour cut-out: 805.72,983.4 803.44,981.12 803.44,961.34 853.29,961.34 853.29,983.58
  pour cut-out: 660.05,869.71 657.77,867.43 657.77,847.65 706.96,847.65 706.96,869.89
  pour cut-out: 802.66,1302.71 800.37,1300.43 800.37,1280.65 849.56,1280.65 849.56,1302.89
  pour cut-out: 2528.15,1570.86 2420.15,1570.86 2420.15,1684.86 2528.15,1684.86
  pour cut-out: 818,1429.14 818,1407.04 853.05,1407.04 853.05,1429.27
  pour cut-out: 545.81,984.28 545.81,962.16 566.68,962.16 566.68,984.36

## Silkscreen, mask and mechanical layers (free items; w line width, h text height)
Top Overlay:
  circle w15: c3569,1950.4 r7.07
  lines w7: 2793,967 2816.33,1007.42
  lines w7.87: 1439.95,1592.63 ccw(c1479.32,1592.63) 1479.32,1553.26 1676.17,1553.26 ccw(c1676.17,1592.63) 1715.54,1592.63 1715.54,1789.48 ccw(c1676.17,1789.48) 1676.17,1828.85 1479.32,1828.85 ccw(c1479.32,1789.48) 1439.95,1789.48 1439.95,1592.63
  text "NORDIC" at 2889.67,2269.92 h150
  text "DUT / select" at 245,2255 h80
  text "SEMICONDUCTOR" at 2886.28,2211.23 h65
  text "DK" at 250,2164 h80
  text "GND" at 2449.32,2145.67 h40
  text "www.nordicsemi.com" at 2694,2138 h83
  text "External" at 250,2084.26 h80
  text "0232RUBR" at 2669.29,1856.01 h65
  text "-" at 545,1822 h60
  text "400102" at 2681.29,1793.01 h80
  text "+" at 545,1723 h60
  text "LABEL" at 1487.94,1672.26 h40
  text "External DUT" at 69.75,1637.55 h80
  text "COM" at 2088.04,1388.15 h90
  text "External  / 5V supply" at 197,1343 h80
  text "DK" at 2034.89,1258.58 h70 r90
  text "EXT" at 2338.27,1253 h70 r90
  text "Power / select" at 161.56,1098.4 h80
  text "TRIG / REF" at 2752,1017 h70
  text "DK" at 183,1000 h80
  text "<" at 2809.25,952.72 h70 r60
  text "5V" at 2720,922 h60
  text "Reg." at 183,900 h80
  text "Debug in" at 2048,867 h80
  text "VDD" at 2720,858 h60
  text "External" at 183,825 h80
  text "EXT" at 2745,781 h60
  text "GND" at 2079.32,673 h80
  text "TRIG IN" at 1995,573 h80
  text "-" at 550.44,548.68 h60
  text "TRIG OUT" at 1927.92,473 h80
  text "+" at 545.81,452.76 h60
  text "TRIGGER" at 2273,355 h80
  text "External DUT supply / 1.8 - 3.6V" at 23,282 h80
  text "S2" at 2607,137 h70 r90
  text "S1" at 2606,41 h70 r90
  text "GND" at 78.74,29.53 h30
Bottom Overlay:
  drawing of 3301 lines, arcs and shapes, not listed
  text "Pb" at 3574,934 h120
Mechanical 1:
  lines w6: 0,0 0,2381.89 3703.69,2381.89 3703.69,752.03 2736.92,752.03 2736.92,0 2600,0 0,0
